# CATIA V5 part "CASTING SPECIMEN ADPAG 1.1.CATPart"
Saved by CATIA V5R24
Part number: PART3
Bounding box of the stored display mesh (mm): x -120.65 to 366.955, y -108.73 to 132.192, z -2.54 to 279.844
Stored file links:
  H:\test\CASTING SPECIMEN ADPAG 1.1.CATPart
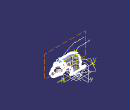
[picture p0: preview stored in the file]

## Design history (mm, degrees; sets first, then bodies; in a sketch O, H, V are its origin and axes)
AxisSystem1: origin (0, 0, 0), X (1, 0, 0), Y (0, 1, 0), Z (0, 0, 1)
f4a2d38f3ddc11d3a929006094b99c4b_11 "CATTPSSet"
TTRSSet1
Set1 "Datum Plane Set"
  Plane1 "Plane -A-": type 3Points, Element1 Point1, Element2 Point2, Element3 Point3
  Plane2 "Plane -B-": type Offset, RefPlane ZX plane of AxisSystem1, Offset 57.15, reversed
  Plane3 "Plane -C-": type Offset, RefPlane YZ plane of AxisSystem1, Offset 57.15, reversed
  Plane4 "Plane -D-": type Offset, RefPlane XY plane of AxisSystem1, Offset 2.54, reversed
Set2
  Plane5: type Normal, Curve Sketch4, RefPoint Sketch4.P3
  Intersect1: ToIntersect1 edge [YZ plane of AxisSystem1 | XY plane of AxisSystem1], ToIntersect2 Sketch1
  Extract1: ExtractElem vertex of Intersect1
  Extremum1: Reference Sketch3, Direction (1, 2, 3)
  Intersect2: ToIntersect1 Sketch3.H, ToIntersect2 Sketch3
  Sweep1: type Circle, Guide Join1, Radius 57.15 {= Sketch1.radius(A1)}, RadiusEnd 38.1 {= Sketch3.radius(A1)}
  Plane6: type OffsetPt, RefPlane XY plane of AxisSystem1, RefPoint Sketch2.P1
  Join1: Elements (Sketch2; Sketch4)
Set3
  Sketch1 on XY plane of AxisSystem1, origin (0, 0, 0), H (1, 0, 0), V (0, 1, 0)
    circle A1 centre (0, 0) radius 57.15
    point P1 (57.15, 0)
    radius A1 = 57.15
    coincidence: A1 P1, P1 H
  Sketch2 on ZX plane of AxisSystem1, origin (0, 0, 0), H (1, 0, 0), V (0, 0, 1)
    line L1 (0, 0) -> (0, 101.6)
    line L2 (101.6, 203.2) -> (203.2, 203.2)
    point P1 (203.2, 203.2)
    arc A1 centre (101.6, 101.6) radius 101.6 from (101.6, 203.2) to (0, 101.6) ccw
    radius A1 = 101.6
    length L1 = 101.6
    distance P1 L1 = 203.2
    vertical: L1 V
    horizontal: L2 H
    tangency: A1 L2, A1 L1
  Sketch3 on Plane5, origin (310.9631, 76.2, 203.2), H (-0.7071, 0.7071, 0), V (0, 0, 1)
    circle A1 centre (0, 0) radius 38.1
    point P1 (-38.1, 0)
    radius A1 = 38.1
    coincidence: A1 P1, P1 H
  Sketch4 on Plane6, origin (203.2, 0, 203.2), H (1, 0, 0), V (0, 1, 0)
    projected line E1 (0, 0) -> (-101.6, 0) from Sketch2.L2
    projected line E2 (0, 0) -> (-101.6, 0) from Sketch2.L2
    line L1 (53.8815, 22.3185) -> (107.7631, 76.2)
    point P3 (107.7631, 76.2)
    arc A1 centre (0, 76.2) radius 76.2 from (0, 0) to (53.8815, 22.3185) ccw
    point P4 (0, 76.2)
    radius A1 = 76.2
    angle L1 H = 45
    length L1 = 76.2
    coincidence: A1 O, P4 V
    tangency: A1 E1, L1 A1
  Sketch5 on end face of Pad4, origin (0, -5.5563, 0), H (0.766, 0, 0.6428), V (-0.6428, 0, 0.766)
  Boundary1: Boundary end face of Pad2
  Extract2: ExtractElem edge of Boundary1
  Intersect3: ToIntersect1 Extract2, ToIntersect2 ZX plane of AxisSystem1
  Extract3: ExtractElem vertex of Intersect3
  Intersect4: ToIntersect1 Extract2, ToIntersect2 ZX plane of AxisSystem1
  Extract4: ExtractElem vertex of Intersect4
  Point1: type Center, Curve edge [end face of Pad2 | face of Pad2 from Sketch9.A1]
  Point2: type Center, Curve edge [end face of Pad2 | face of Pad2 from Sketch9.A3]
  Point3: type Center, Curve edge [end face of Pad2 | face of Pad2 from Sketch9.A2]
  Circle1: type CtrRad, Start 0, End 180, Center Point1, Support end face of Pad2, Radius 12.7, FirstDirection (1, 0, 0)
  Circle2: type CtrRad, Start 0, End 180, Center Point2, Support end face of Pad2, Radius 12.7, FirstDirection (1, 0, 0)
  Circle3: type CtrRad, Start 0, End 180, Center Point3, Support end face of Pad2, Radius 12.7, FirstDirection (1, 0, 0)
Set4 "Surface Refinment"
  Fill1: Boundary Circle2
  Fill2: Boundary Circle1
  Fill3: Boundary Circle3
  Fill4: Boundary ({fillboundary BoundaryWire edge [end face of Pad4 | face of Fillet5], Support end face of Pad4}; edge [end face of Pad4 | face of Fillet5]; edge [end face of Pad4 | face of Fillet5]; edge [end face of Pad4 | face of Fillet5])
Set5 "Parting lines 5 section mold"
  Point4: type Center, Curve edge [face of Pad3 from Sketch10.A2 | face of Pad3]
  Plane7: type 3Points, Element1 Sketch4.P3, Element2 vertex [element of Sketch4 | element of Sketch4], Element3 Point4
  Plane8: type Angle, RefPlane Plane7, Direction Sketch4.L1, Angle 90
  Sketch6 on ZX plane of AxisSystem1, origin (0, 0, 0), H (1, 0, 0), V (0, 0, 1)
    line L1 (-57.15, 63.5) -> (-57.15, 88.9)
    line L2 (-57.15, 88.9) -> (-56.8111, 88.9)
    arc A1 centre (-56.8111, 92.0751) radius 3.1751 from (-56.8111, 88.9) to (-53.6384, 91.9539) ccw
    line L3 (-53.6384, 91.9539) -> (-53.27, 101.6)
    unspec C1
    line L4 (101.6, 250.3754) -> (203.2, 246.4955)
    line L5 (203.2, 159.9045) -> (178.8365, 158.9741)
    arc A2 centre (179.8058, 133.5926) radius 25.4001 from (178.8365, 158.9741) to (163.479, 153.0502) ccw
    line L6 (163.479, 153.0502) -> (64.3175, 69.8438)
    arc A3 centre (80.6444, 50.3863) radius 25.4 from (64.3175, 69.8438) to (55.2628, 49.417) ccw
    line L7 (55.2628, 49.417) -> (55.844, 34.198)
    arc A4 centre (74.8801, 34.9249) radius 19.0499 from (55.844, 34.198) to (74.8801, 15.875) ccw
    line L8 (74.8801, 15.875) -> (76.2, 15.875)
    line L9 (76.2, 15.875) -> (76.2, -2.54)
    line L10 (76.2, -2.54) -> (-120.65, -2.54)
    line L11 (-120.65, -2.54) -> (-120.65, 15.875)
    line L12 (-120.65, 15.875) -> (-68.7766, 15.875)
    arc A5 centre (-68.7766, 28.5839) radius 12.7089 from (-68.7766, 15.875) to (-56.0769, 28.0989) ccw
    line L13 (-56.0769, 28.0989) -> (-54.8463, 60.3251)
    arc A6 centre (-58.019, 60.4462) radius 3.175 from (-54.8463, 60.3251) to (-57.15, 63.5) ccw
  Boundary2: Boundary face of CloseSurface1
  Extract5: ExtractElem edge of Boundary2
  Sketch7 on Plane6, origin (0, 0, 203.2), H (1, 0, 0), V (0, 1, 0)
    unspec C1
    unspec C2
    line L1 (318.1403, 27.9263) -> (286.08, -6.68)
    line L2 (228.0831, 51.3169) -> (262.6893, 83.3772)
    arc A1 centre (327.4567, 19.2954) radius 12.6999 from (336.4369, 28.2755) to (318.1403, 27.9263) ccw
    arc A2 centre (254.0585, 92.6936) radius 12.6999 from (262.6893, 83.3772) to (263.0386, 101.6739) ccw
  Boundary3: Boundary end face of Pad3
  Extract6: ExtractElem edge of Boundary3
  Boundary4: Boundary end face of Pad3
  Extract7: ExtractElem edge of Boundary4
Body1 (main body)
  Sketch8 on ZX plane of AxisSystem1, origin (0, 0, 0), H (1, 0, 0), V (0, 0, 1)
    line L1 (0, 15.875) -> (223.2452, 203.2)
    point P1 (0, 15.875)
    point P2 (223.2452, 203.2)
    reference projected point E1 (203.2, 203.2) from Sketch2.P1
    distance P1 H = 15.875
    angle L1 H = 40
    distance P2 E1 V = 0
    distance E1 P2 = 20.0452 (reference)
    coincidence: P1 V
  CloseSurface1: CloseElement Sweep1
  Shell1: ExtOffset 0, Face (face of CloseSurface1; face of CloseSurface1), IntOffset 6.35
  ThickSurface1: BotOffset 0, Surface face of CloseSurface1, TopOffset 2.54
  ThickSurface2: BotOffset 0, Surface face of CloseSurface1, TopOffset 2.54
  Pad1: profile Sketch8, direction (0, -1, 0), length 4.7625, mirrored extent
  Fillet1: radius 6.35, on edge [start face of Pad1 | face of CloseSurface1] (x3); edge [face of CloseSurface1 | end face of Pad1] (x3)
  Fillet2: radius 25.4, on edge [face of Pad1 from Sketch8.L1 | face of CloseSurface1] (x2)
  Sketch9 on XY plane of AxisSystem1, origin (0, 0, 0), H (-1, 0, 0), V (0, 1, 0)
    arc A1 centre (88.9, 0) radius 31.75 from (104.775, -27.4963) to (104.775, 27.4963) ccw
    point P1 (88.9, 0)
    arc A2 centre (-44.45, 76.9897) radius 31.75 from (-28.575, 104.486) to (-76.2, 76.9897) ccw
    point P2 (-44.45, 76.9897)
    arc A3 centre (-44.45, -76.9897) radius 31.75 from (-76.2, -76.9897) to (-28.575, -104.486) ccw
    point P3 (-44.45, -76.9897)
    line L1 (-28.575, 104.486) -> (104.775, 27.4963)
    line L2 (104.775, -27.4963) -> (-28.575, -104.486)
    line L3 (-76.2, 76.9897) -> (-76.2, -76.9897)
    construction circle A4 centre (0, 0) radius 88.9
    point P10 (0, 0)
    offset circle E2 centre (0, 0) radius 54.61 from Sketch1.A1
    radius A2 = 31.75
    radius A1 = 31.75
    radius A3 = 31.75
    distance P1 V = 88.9
    angle L1 H = 30
    angle L3 L1 = 60 (reference)
    radius A4 = 88.9
    coincidence: P1 H, A4 P1, A4 P3, A4 P2, P10 H
    tangency: L1 A1, L2 A3, L3 A3, L2 A1, A2 L1, A2 L3
    vertical: L3 V
  Pad2: profile Sketch9, direction (0, 0, 1), length 15.875, opposite side up to Plane4
  Sketch10 on Plane5, origin (310.9631, 76.2, 203.2), H (-0.7071, 0.7071, 0), V (0, 0, 1)
    offset circle E2 centre (0, 0) radius 35.56 from Sketch3.A1
    construction circle A1 centre (0, 0) radius 63.5
    point P1 (44.9013, 44.9013)
    arc A2 centre (44.9013, 44.9013) radius 31.75 from (74.4579, 33.3052) to (33.3052, 74.4579) ccw
    arc A3 centre (-44.9013, -44.9013) radius 31.75 from (-74.4579, -33.3052) to (-33.3052, -74.4579) ccw
    point P2 (-44.9013, -44.9013)
    arc A4 centre (0, 0) radius 57.15 from (-20.873, 53.2019) to (-53.2019, 20.873) ccw
    line L1 (-74.4579, -33.3052) -> (-53.2019, 20.873)
    line L2 (-20.873, 53.2019) -> (33.3052, 74.4579)
    line L3 (74.4579, 33.3052) -> (53.2019, -20.873)
    line L4 (-33.3052, -74.4579) -> (20.873, -53.2019)
    arc A5 centre (0, 0) radius 57.15 from (20.873, -53.2019) to (53.2019, -20.873) ccw
    construction circle A6 centre (44.9013, 44.9013) radius 31.75
    point P11 (33.3052, 74.4579)
    construction line L5 (0, 0) -> (44.9013, 44.9013)
    point P12 (0, 0)
    point P13 (44.9013, 44.9013)
    radius A1 = 63.5
    radius A3 = 31.75
    radius A2 = 31.75
    radius A4 = 57.15
    angle L2 H = 338.5782 (reference)
    angle L5 H = 45
    coincidence: A1 P1, P2 A1, A4 A5, A6 P11, P11 L2, P11 A2, P12 H, P13 A1, L5 P2, P13 P1, L5 O
    tangency: L1 A4, L2 A2, L3 A2, L4 A4, A3 L1, A3 L4, A4 L2, A5 L3
  Pad3: profile Sketch10, direction (-0.7071, -0.7071, 0), length 15.875, opposite side length 2.54
  Fillet3: on edge [end face of Pad2 | face of CloseSurface1]
  Fillet4: radius 12.7, on edge [face of CloseSurface1 | end face of Pad3]
  Sketch11 on end face of Pad1, origin (0, -4.7625, 0), H (0.766, 0, 0.6428), V (-0.6428, 0, 0.766)
    point P1 (116.1253, 40.101)
    line L1 (116.1253, 40.101) -> (179.6253, 40.101)
    line L2 (179.6253, 40.101) -> (179.6253, 14.701)
    line L3 (179.6253, 14.701) -> (116.1253, 14.701)
    line L4 (116.1253, 14.701) -> (116.1253, 40.101)
    point P2 (179.6253, 40.101)
    reference projected line E1 (93.9868, 12.161) -> (223.8768, 12.161) from edge [face of Pad1 from Sketch8.L1 | end face of Pad1]
    reference projected curve E3 from edge [end face of Pad1 | face of Fillet1]
    reference projected line E4 (175.0593, 50.028) -> (223.9441, 12.161) from edge [end face of Pad1 | face of Fillet1]
    distance L3 E1 = 2.54
    distance L1 L3 = 25.4
    distance L2 L4 = 63.5
    distance P1 E3 = 4.7625
    distance P2 E4 = 5.0518 (reference)
    horizontal: L1 H, L3 H
    vertical: L2 V, L4 V
  Pad4: profile Sketch11, direction (0, -1, 0), length 0.7938
  Fillet5: radius 0.7938, on edge [end face of Pad1 | face of Pad4 from Sketch11.L4]; edge [end face of Pad1 | face of Pad4 from Sketch11.L3]; edge [end face of Pad1 | face of Pad4 from Sketch11.L2]; edge [end face of Pad1 | face of Pad4 from Sketch11.L1]
  Sketch12 on Plane2, origin (0, -57.15, 0), H (1, 0, 0), V (0, 0, 1)
    circle A1 centre (0, 76.2) radius 12.7
    point P1 (0, 76.2)
    circle A2 centre (127, 203.2) radius 12.7
    point P2 (127, 203.2)
    reference projected line E1 (203.2, 203.2) -> (101.6, 203.2) from Sketch2.L2
    distance P2 P1 H = 127
    radius A1 = 12.7
    radius A2 = 12.7
    distance P1 H = 76.2
    coincidence: P1 V, P2 E1
  Pad5: profile Sketch12, direction (0, 1, 0), up to the existing solid (limit type 2)
  Draft1: Angle 1, Neutral start face of Pad5, PullDir start face of Pad5, SupportToDraft (face of Pad5 from Sketch12.A2; face of Pad5 from Sketch12.A1)
  Sketch13 on Plane3, origin (-57.15, 0, 0), H (0, -1, 0), V (0, 0, 1)
    circle A1 centre (0, 76.2) radius 12.7
    point P1 (0, 76.2)
    radius A1 = 12.7
    distance P1 H = 76.2
    coincidence: P1 V
  Pad6: profile Sketch13, direction (1, 0, 0), up to the existing solid (limit type 2)
  Fillet6: radius 3.175, on edge [face of Pad6 from Sketch13.A1 | face of CloseSurface1]; edge [face of Pad5 from Sketch12.A1 | face of CloseSurface1]; edge [face of Pad5 from Sketch12.A2 | face of CloseSurface1]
